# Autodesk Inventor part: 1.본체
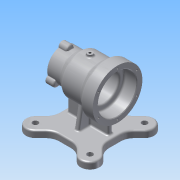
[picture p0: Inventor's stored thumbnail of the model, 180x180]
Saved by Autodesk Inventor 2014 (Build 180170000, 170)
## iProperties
Created: 2017-03
Part Number: 1.본체
Material: 알루미늄 6061
Document SubType Name: Modeling
Designer: 00
Density: 2.71 g/cm^3
Appearance: 알루미늄 - 평지
Author: 00
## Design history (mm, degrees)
sketch "스케치2"
  geometry: L1 (-20.958, 45)-(20.958, 45); L2 (-45, -20.958)-(-45, 20.958); L3 (0, 0)-(98.995, 0); L4 (-37.477, 61.518)-(-20.958, 45); L5 (-61.518, 37.477)-(-45, 20.958); L6 (-61.518, -37.477)-(-45, -20.958); L7 (-37.477, -61.518)-(-20.958, -45); L8 (37.477, -61.518)-(20.958, -45); L9 (61.518, -37.477)-(45, -20.958); L10 (61.518, 37.477)-(45, 20.958); L11 (37.477, 61.518)-(20.958, 45); L12 (45, 20.958)-(45, -20.958); L13 (20.958, -45)-(-20.958, -45); A1 r 17 centre (-49.497, 49.497) between (-37.477, 61.518) and (-61.518, 37.477); A2 r 17 centre (-49.497, -49.497) between (-61.518, -37.477) and (-37.477, -61.518); A3 r 17 centre (49.497, -49.497) between (37.477, -61.518) and (61.518, -37.477); A4 r 17 centre (49.497, 49.497) between (61.518, 37.477) and (37.477, 61.518); 2 further points
  constraints: 26 end point, 8 point on circle, 4 centre point, 3 horizontal, 3 tangent, 2 coincident, 1 parallel, 1 vertical, 33 other
  dimensions: "d19" = 34 diameter of A1; "d22" = 360 deg dimension on point (0, 0) A1.centre (derived); "d24" = 45 deg angle of L10 L3; "d25" = 45 distance between parallel lines of L3 L1; "d26" = 53 distance from line of L3.end L10; "d28" = 37.47666 distance from line of L10.start L3
extrude "돌출1" new body sketch "스케치2" distance "d29" = 12; taper "d30" = 0 deg
fillet "모깎기1" dims "d31" = 25
sketch "스케치3"
  geometry: L1 (-45, 0)-(-45, 12) reference; L2 (-45, 12)-(45, 12) reference; L3 (45, 12)-(45, 0) reference; L4 (45, 0)-(-45, 0) reference; L5 (50, 82)-(-50, 82); L6 (-50, 82)-(-50, 127); L7 (-50, 127)-(-30, 127); L8 (-30, 127)-(-19, 118); L9 (-19, 118)-(15, 118); L10 (15, 118)-(27, 109.5); L11 (27, 109.5)-(50, 109.5); L12 (50, 109.5)-(50, 82); 1 further point
  constraints: 16 end point, 4 horizontal, 2 vertical
  dimensions: "d34" = 45 distance of L5.end L6.end; "d35" = 20 distance of L6.end L7.end; "d36" = 31 horizontal distance of L8.end L6.end; "d37" = 72 diameter of L8.end L5; "d38" = 65 horizontal distance of L9.end L6.end; "d39" = 55 diameter of L10.end L5; "d40" = 23 distance of L11.end L10.end; "d74" = 100 horizontal distance of L11.end L6.end; "d75" = 95 distance between parallel lines of L1 L12; "d76" = 109.5 distance between parallel lines of L4 L11
revolve "회전1" sketch "스케치3" stored, may be unused: angle "d45" = 90 deg
sketch "스케치5"
  geometry: A1 r 27.5 centre (0, 0) between (26.609, -6.943) and (26.609, 6.943) reference; A2 r 7 centre (27.5, 0) between (26.609, -6.943) and (26.609, 6.943); A3 r 7 centre (-13.75, 23.816) between (-7.292, 26.516) and (-19.317, 19.573); A4 r 7 centre (-13.75, -23.816) between (-19.317, -19.573) and (-7.292, -26.516); A5 r 27.5 centre (0, 0) between (26.609, -6.943) and (26.609, 6.943); A6 r 27.5 centre (0, 0) between (-7.292, 26.516) and (-19.317, 19.573); A7 r 27.5 centre (0, 0) between (-19.317, -19.573) and (-7.292, -26.516); 1 further point
  constraints: 15 point on circle, 6 centre point, 1 coincident, 13 other
  dimensions: "d57" = 14 diameter of A2; "d60" = 360 deg dimension on A1.centre A2.centre (derived); "d62" = 109.5 distance of point (-82, 0) A2.centre
extrude "돌출2" join sketch "스케치5" distance "d63" = 15; taper "d64" = 0 deg
sketch "스케치6"
  geometry: C1 r 45 at (0, 0) reference; C2 r 35 at (0, 0); 1 further point
  constraints: 1 centre point, 1 coincident
  dimensions: "d65" = 70 diameter of C2
extrude "돌출3" cut sketch "스케치6" distance "d66" = 23; taper "d67" = 0 deg
sketch "스케치7"
  geometry: C1 r 35 at (0, 0) reference; C2 r 26 at (0, 0); 1 further point
  constraints: 1 centre point, 1 coincident
  dimensions: "d68" = 52 diameter of C2
extrude "돌출4" cut sketch "스케치7" distance "d69" = 47; taper "d70" = 0 deg
sketch "스케치8"
  geometry: C1 r 26 at (0, 0) reference; C2 r 17.5 at (0, 0); 1 further point
  constraints: 1 centre point, 1 coincident
  dimensions: "d71" = 35 diameter of C2
extrude "돌출5" cut sketch "스케치8" distance "d72" = 30; taper "d73" = 0 deg
sketch "스케치9"
  geometry: 2 further points
hole "구멍1" sketch "스케치9" at (-40, 0) diameter "d78" = 3.242; stored, may be unused: countersink angle "d82" = 90 deg, drill point angle "d84" = 118 deg; dims "d79" = 9, "d80" = 4, "d81" = 2, "d83" = 11
sketch "스케치10"
  geometry: A1 r 7 centre (0, 0) between (-0.891, -6.943) and (-0.891, 6.943) reference; 2 further points
  constraints: 1 coincident
hole "구멍2" sketch "스케치10" at (0, 0) diameter "d90" = 3.242; stored, may be unused: countersink angle "d94" = 90 deg, drill point angle "d96" = 118 deg; dims "d91" = 9, "d92" = 4, "d93" = 2, "d95" = 11
sketch "스케치11"
  geometry: L1 (45, 12)-(45, 0) reference; L2 (45, 0)-(-45, 0) reference; L3 (-45, 0)-(-45, 12) reference; L4 (-45, 12)-(45, 12) reference; L5 (0, 12)-(25, 12); L6 (25, 12)-(17.242, 56); L7 (17.242, 56)-(0, 48.168); L8 (-17.242, 56)-(0, 48.168); L9 (-25, 12)-(-17.242, 56); L10 (0, 12)-(-25, 12); C1 r 26 at (0, 82) reference; C2 r 36 at (0, 82) reference; 1 further point
  constraints: 12 end point, 1 midpoint, 1 point on line
  dimensions: "d100" = 25 distance of L5.start L5.end; "d101" = 80 deg angle of L6 L5; "d102" = 65.571 deg angle of L1 L7; "d103" = 114.429 deg angle of L1 L8; "d104" = 90 deg angle of L1 L10; "d107" = 14.31992 distance from line of L1.start L8; "d108" = 68.93654 distance from line of L1.start L9; "d109" = 80 deg angle of L2 L9; "d110" = 51.54078 distance from line of L1.start L7
extrude "돌출6" join sketch "스케치11" stored distance "d111" = 8; taper "d112" = 0 deg
sketch "스케치12"
  geometry: L1 (35, 116.5)-(50, 116.5) reference; L2 (50, 116.5)-(50, 111.121) reference; L3 (50, 111.121)-(39, 111.121) reference; L4 (39, 111.121)-(38.026, 109.5) reference; L5 (38.026, 109.5)-(39, 107.879) reference; L6 (39, 107.879)-(50, 107.879) reference; L7 (50, 107.879)-(50, 99.5) reference; L8 (50, 99.5)-(20, 99.5) reference; L9 (20, 99.5)-(20, 108) reference; L10 (20, 108)-(-27, 108) reference; L11 (-27, 108)-(-27, 117) reference; L12 (-27, 117)-(-50, 117) reference; L13 (-50, 117)-(-50, 120.379) reference; L14 (-50, 120.379)-(-39, 120.379) reference; L15 (-39, 120.379)-(-38.026, 122) reference; L16 (-38.026, 122)-(-39, 123.621) reference; L17 (-39, 123.621)-(-50, 123.621) reference; L18 (-50, 123.621)-(-50, 127) reference; L19 (-50, 127)-(-30, 127) reference; L20 (-30, 127)-(-19, 118) reference; L21 (-19, 118)-(15, 118) reference; L22 (15, 118)-(27, 109.5) reference; L23 (27, 109.5)-(35, 109.5) reference; L24 (35, 109.5)-(35, 116.5) reference; L25 (-45, 0)-(-45, 12) reference; L26 (-45, 12)-(-4, 12) reference; L27 (-4, 12)-(-4, 46) reference; L28 (-4, 46)-(-19, 46) reference; L29 (-19, 46)-(-30, 37) reference; L30 (-30, 37)-(-50, 37) reference; L31 (-50, 37)-(-50, 40.379) reference; L32 (-50, 40.379)-(-39, 40.379) reference; L33 (-39, 40.379)-(-38.026, 42) reference; L34 (-38.026, 42)-(-39, 43.621) reference; L35 (-39, 43.621)-(-50, 43.621) reference; L36 (-50, 43.621)-(-50, 47) reference; L37 (-50, 47)-(-27, 47) reference; L38 (-27, 47)-(-27, 56) reference; L39 (-27, 56)-(20, 56) reference; L40 (20, 56)-(20, 64.5) reference; L41 (20, 64.5)-(50, 64.5) reference; L42 (50, 64.5)-(50, 54.5) reference; L43 (50, 54.5)-(27, 54.5) reference; L44 (27, 54.5)-(15, 46) reference; L45 (15, 46)-(4, 46) reference; L46 (4, 46)-(4, 12) reference; L47 (4, 12)-(45, 12) reference; L48 (45, 12)-(45, 0) reference; L49 (45, 0)-(-45, 0) reference; L50 (0, 12)-(-37, 12); L51 (-37, 12)-(-37, 40.379); L52 (-37, 40.379)-(-14.466, 50.25); L53 (-14.466, 50.25)-(0, 50.25); L54 (0, 12)-(37, 12); L55 (37, 12)-(37, 59.5); L56 (37, 59.5)-(21, 54.5); L57 (21, 54.5)-(13.927, 50.25); L58 (13.927, 50.25)-(0, 50.25); 1 further point
  constraints: 18 end point, 2 horizontal, 2 point on line, 2 vertical, 1 perpendicular
  dimensions: "d114" = 37 distance of L50.start L50.end; "d115" = 37 distance of L50.start L54.end; "d116" = 107.354 deg angle of L2 L56; "d117" = 113.655 deg angle of L2 L52; "d118" = 59 deg angle of L4 L54; "d119" = 13 distance between parallel lines of L2 L55; "d120" = 60.871 distance between parallel lines of L3 L53; "d121" = 50.52778 distance from line of L1.end L56; "d122" = 38.20827 distance from line of L1.end L57; "d123" = 34.81738 distance from line of L1.end L52; "d124" = 50 distance from line of L53.end L2
extrude "돌출7" join sketch "스케치12" stored distance "d125" = 8; taper "d126" = 0 deg
sketch "스케치13"
  geometry: C1 r 5 at (-49.497, 49.497); C2 r 5 at (49.497, 49.497); C3 r 5 at (-49.497, -49.497); C4 r 5 at (49.497, -49.497); A1 r 17 centre (-49.497, -49.497) between (-61.518, -37.477) and (-37.477, -61.518) reference; A2 r 17 centre (49.497, -49.497) between (37.477, -61.518) and (61.518, -37.477) reference; A3 r 17 centre (49.497, 49.497) between (61.518, 37.477) and (37.477, 61.518) reference; A4 r 17 centre (-49.497, 49.497) between (-37.477, 61.518) and (-61.518, 37.477) reference; 1 further point
  constraints: 4 centre point, 4 coincident
  dimensions: "d127" = 10 diameter of C1; "d128" = 10 diameter of C2; "d129" = 10 diameter of C3; "d130" = 10 diameter of C4
extrude "돌출8" cut sketch "스케치13" distance "d131" = 12; taper "d132" = 0 deg
fillet "모깎기2" dims "d133" = 3
fillet "모깎기3" dims "d134" = 3
fillet "모깎기4" dims "d135" = 3
fillet "모깎기5" dims "d136" = 1
fillet "모깎기7" dims "d138" = 3
fillet "모깎기8" dims "d139" = 1
fillet "모깎기9" dims "d140" = 3
chamfer "모따기1" distance "d141" = 1; stored, may be unused: second distance "d142" = 2, angle "d143" = 45 deg
chamfer "모따기2" distance "d144" = 1; stored, may be unused: second distance "d145" = 2, angle "d146" = 45 deg
fillet "모깎기10" dims "d147" = 3
fillet "모깎기11" dims "d148" = 3
node "작업 평면1"
sketch "스케치16"
  geometry: L1 (39, 1.621)-(38.026, 0) reference; L2 (38.026, 0)-(39, -1.621) reference; L3 (39, -1.621)-(50, -1.621) reference; L4 (50, -1.621)-(50, -20.616) reference; L5 (50, -20.616)-(31, -20.616) reference; L6 (31, 20.616)-(50, 20.616) reference; L7 (50, 20.616)-(50, 1.621) reference; L8 (50, 1.621)-(39, 1.621) reference; C1 r 5 at (0, 0); 3 further points
  constraints: 1 centre point, 1 coincident, 1 vertical alignment, 2 other
  dimensions: "d151" = 10 diameter of C1
extrude "돌출9" join sketch "스케치16" stored distance "d152" = 10; taper "d153" = 0 deg
hole "구멍3" diameter "d156" = 4.134; stored, may be unused: countersink angle "d160" = 82 deg, drill point angle "d162" = 0 deg; dims "d154" = 10, "d155" = 10, "d157" = 14, "d158" = 3.023, "d159" = 2, "d161" = 14
fillet "모깎기12" dims "d163" = 3
sketch "스케치18"
  geometry: L1 (-42, 10.603)-(-42, -10.603) reference; L2 (-59.397, 39.598)-(-50.201, 30.402) reference; L3 (-30.402, 50.201)-(-39.598, 59.397) reference; L4 (10.603, 42)-(-10.603, 42) reference; L5 (39.598, 59.397)-(30.402, 50.201) reference; L6 (50.201, 30.402)-(59.397, 39.598) reference; L7 (42, -10.603)-(42, 10.603) reference; L8 (59.397, -39.598)-(50.201, -30.402) reference; L9 (30.402, -50.201)-(39.598, -59.397) reference; L10 (-10.603, -42)-(10.603, -42) reference; L11 (-39.598, -59.397)-(-30.402, -50.201) reference; L12 (-50.201, -30.402)-(-59.397, -39.598) reference; L13 (7, -21.425)-(7, -7) reference; L14 (7, -7)-(34, -7) reference; L15 (40, -1)-(40, 1) reference; L16 (34, 7)-(7, 7) reference; L17 (7, 7)-(7, 21.425) reference; L18 (1, 27.517)-(-1, 27.517) reference; L19 (-7, 21.425)-(-7, 7) reference; L20 (-7, 7)-(-34, 7) reference; L21 (-40, 1)-(-40, -1) reference; L22 (-34, -7)-(-7, -7) reference; L23 (-7, -7)-(-7, -21.425) reference; L24 (-1, -27.517)-(1, -27.517) reference; L25 (-45, 10.603)-(-45, -10.603) reference; C1 r 5 at (-49.497, -49.497) reference; C2 r 5 at (-49.497, 49.497) reference; C3 r 5 at (49.497, 49.497) reference; C4 r 5 at (49.497, -49.497) reference; A1 r 28 centre (-70, -10.603) between (-50.201, -30.402) and (-42, -10.603) reference; A2 r 28 centre (-70, 10.603) between (-42, 10.603) and (-50.201, 30.402) reference; A3 r 14 centre (-49.497, 49.497) between (-39.598, 59.397) and (-59.397, 39.598) reference; A4 r 28 centre (-10.603, 70) between (-30.402, 50.201) and (-10.603, 42) reference; A5 r 28 centre (10.603, 70) between (10.603, 42) and (30.402, 50.201) reference; A6 r 14 centre (49.497, 49.497) between (59.397, 39.598) and (39.598, 59.397) reference; A7 r 28 centre (70, 10.603) between (50.201, 30.402) and (42, 10.603) reference; A8 r 28 centre (70, -10.603) between (42, -10.603) and (50.201, -30.402) reference; A9 r 14 centre (49.497, -49.497) between (39.598, -59.397) and (59.397, -39.598) reference; A10 r 28 centre (10.603, -70) between (30.402, -50.201) and (10.603, -42) reference; A11 r 28 centre (-10.603, -70) between (-10.603, -42) and (-30.402, -50.201) reference; A12 r 14 centre (-49.497, -49.497) between (-59.397, -39.598) and (-39.598, -59.397) reference; A13 r 6 centre (34, -1) between (34, -7) and (40, -1) reference; A14 r 6 centre (34, 1) between (40, 1) and (34, 7) reference; A15 r 6 centre (-34, 1) between (-34, 7) and (-40, 1) reference; A16 r 6 centre (-34, -1) between (-40, -1) and (-34, -7) reference; 2 further points
  constraints: 5 other
  dimensions: "d164" = 35 distance of point (0, 0) point (0, 35); "d165" = 45 distance from line of L25 point (0, 35)
feature "엠보싱1" sketch "스케치18" dims "d19" = 34, "d22" = 360 deg (derived), "d24" = 45 deg, "d25" = 45, "d26" = 53, "d28" = 37.47666, "d166" = 0.5, "d167" = 0
node "솔리드1"
pattern_circular "원형 패턴1" dims angle "d86" = 360 deg
pattern_circular "원형 패턴2" dims angle "d98" = 360 deg
node "절단 모서리 투영1"
node "절단 모서리 투영3"
node "절단 모서리 투영4"
node "절단 모서리 투영7"
node "절단 모서리 투영9"
other parameters: "d150" = 122
